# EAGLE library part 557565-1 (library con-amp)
AMP connector
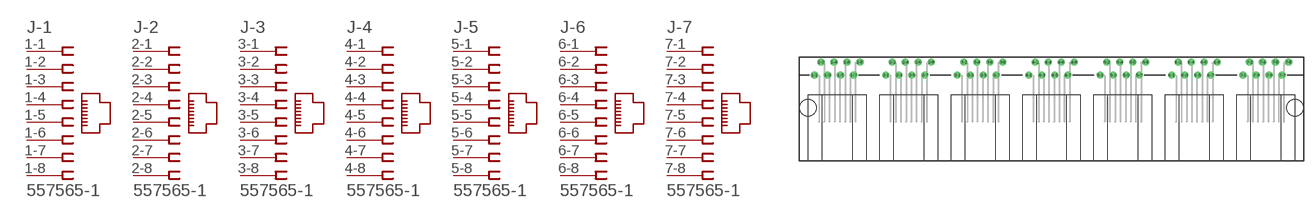
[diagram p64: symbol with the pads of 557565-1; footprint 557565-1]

Designator prefix J; gates -1=JACK8 -2=JACK8 -3=JACK8 -4=JACK8 -5=JACK8 -6=JACK8 -7=JACK8

## 557565-1 (OC_FARNELL: unknown; OC_NEWARK: unknown)  [557565-1]
1-1  -1:1  pas
1-2  -1:2  pas
1-3  -1:3  pas
1-4  -1:4  pas
1-5  -1:5  pas
1-6  -1:6  pas
1-7  -1:7  pas
1-8  -1:8  pas
2-1  -2:1  pas
2-2  -2:2  pas
2-3  -2:3  pas
2-4  -2:4  pas
2-5  -2:5  pas
2-6  -2:6  pas
2-7  -2:7  pas
2-8  -2:8  pas
3-1  -3:1  pas
3-2  -3:2  pas
3-3  -3:3  pas
3-4  -3:4  pas
3-5  -3:5  pas
3-6  -3:6  pas
3-7  -3:7  pas
3-8  -3:8  pas
4-1  -4:1  pas
4-2  -4:2  pas
4-3  -4:3  pas
4-4  -4:4  pas
4-5  -4:5  pas
4-6  -4:6  pas
4-7  -4:7  pas
4-8  -4:8  pas
5-1  -5:1  pas
5-2  -5:2  pas
5-3  -5:3  pas
5-4  -5:4  pas
5-5  -5:5  pas
5-6  -5:6  pas
5-7  -5:7  pas
5-8  -5:8  pas
6-1  -6:1  pas
6-2  -6:2  pas
6-3  -6:3  pas
6-4  -6:4  pas
6-5  -6:5  pas
6-6  -6:6  pas
6-7  -6:7  pas
6-8  -6:8  pas
7-1  -7:1  pas
7-2  -7:2  pas
7-3  -7:3  pas
7-4  -7:4  pas
7-5  -7:5  pas
7-6  -7:6  pas
7-7  -7:7  pas
7-8  -7:8  pas

## Footprint 557565-1 (pad centres in mm)
Modular Jack
drill 0.889 round: 1-1 -46.355,6.35; 1-2 -45.085,8.89; 1-3 -43.815,6.35; 1-4 -42.545,8.89; 1-5 -41.275,6.35; 1-6 -40.005,8.89; 1-7 -38.735,6.35; 1-8 -37.465,8.89; 2-1 -32.385,6.35; 2-2 -31.115,8.89; 2-3 -29.845,6.35; 2-4 -28.575,8.89; 2-5 -27.305,6.35; 2-6 -26.035,8.89; 2-7 -24.765,6.35; 2-8 -23.495,8.89; 3-1 -18.415,6.35; 3-2 -17.145,8.89; 3-3 -15.875,6.35; 3-4 -14.605,8.89; 3-5 -13.335,6.35; 3-6 -12.065,8.89; 3-7 -10.795,6.35; 3-8 -9.525,8.89; 4-1 -4.445,6.35; 4-2 -3.175,8.89; 4-3 -1.905,6.35; 4-4 -0.635,8.89; 4-5 0.635,6.35; 4-6 1.905,8.89; 4-7 3.175,6.35; 4-8 4.445,8.89; 5-1 9.525,6.35; 5-2 10.795,8.89; 5-3 12.065,6.35; 5-4 13.335,8.89; 5-5 14.605,6.35; 5-6 15.875,8.89; 5-7 17.145,6.35; 5-8 18.415,8.89; 6-1 23.495,6.35; 6-2 24.765,8.89; 6-3 26.035,6.35; 6-4 27.305,8.89; 6-5 28.575,6.35; 6-6 29.845,8.89; 6-7 31.115,6.35; 6-8 32.385,8.89; 7-1 37.465,6.35; 7-2 38.735,8.89; 7-3 40.005,6.35; 7-4 41.275,8.89; 7-5 42.545,6.35; 7-6 43.815,8.89; 7-7 45.085,6.35; 7-8 46.355,8.89
hole 3.251 at -47.625,0
hole 3.251 at 47.625,0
